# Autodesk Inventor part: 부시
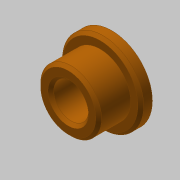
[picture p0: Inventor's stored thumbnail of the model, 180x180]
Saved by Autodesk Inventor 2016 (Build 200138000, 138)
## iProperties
Created: 2016-02
Part Number: 부시
Material: 강철, 연강
Document SubType Name: Modeling
Designer: test
Density: 1 g/cm^3
Appearance: 주황색
Author: test
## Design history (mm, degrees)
sketch "스케치1"
  geometry: C1 r 14 at (0, 0); C2 r 10.5 at (0, 0); 1 further point
  constraints: 2 centre point, 2 coincident
  dimensions: "d0" = 28 diameter of C1; "d1" = 21 diameter of C2
extrude "돌출1" new body sketch "스케치1" distance "d2" = 4; taper "d3" = 0 deg
extrude "돌출2" join sketch "스케치1" distance "d4" = 11; taper "d5" = 0 deg
hole "구멍1" diameter "d8" = 12; stored, may be unused: countersink angle "d12" = 90 deg, drill point angle "d14" = 118 deg; dims "d6" = 10, "d7" = 10, "d9" = 6, "d10" = 4, "d11" = 2, "d13" = 8
chamfer "모따기1" distance "d15" = 1; stored, may be unused: second distance "d16" = 2, angle "d17" = 45 deg
chamfer "모따기2" distance "d18" = 1; stored, may be unused: second distance "d19" = 2, angle "d20" = 45 deg
node "솔리드1"
